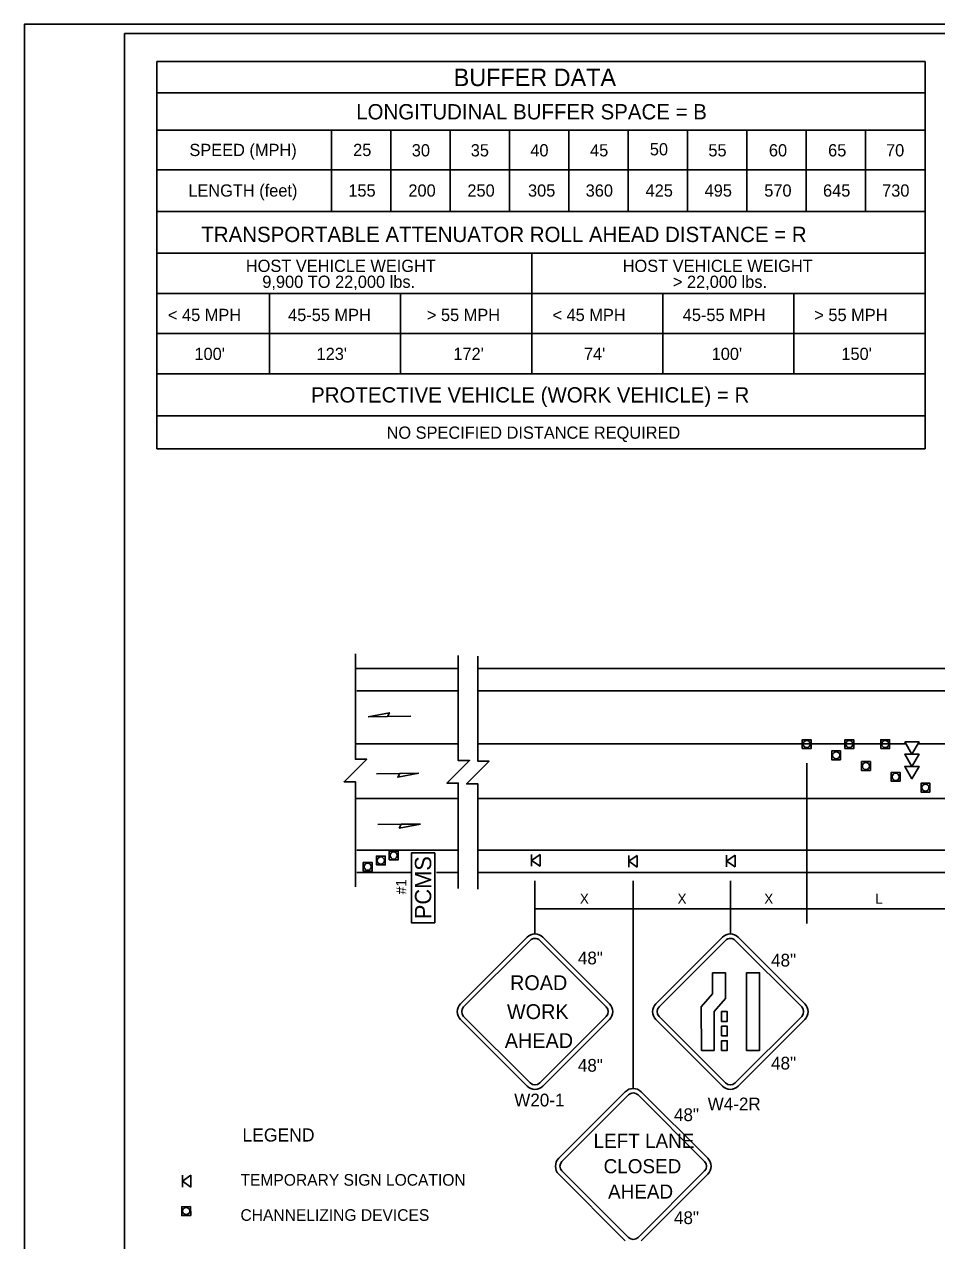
# Model space of a CAD drawing. Extents: x 99988 to 100172, y 99995 to 100047.
# Drawn here: x 99999.31 to 100005.57, y 100002.09 to 100010.44 of the extents above; entities that cross this region are included whole.
import ezdxf

# ---------------------------------------------------------------- set-up
doc = ezdxf.new("R2010")
doc.units = 0
for name, color, linetype in [('Default', 7, 'Continuous'), ('Level 15', 7, 'Continuous'), ('Level 20', 7, 'Continuous'), ('SH_DE_DetailBody1Text', 7, 'Continuous'), ('SH_DE_DetailHeading2Text', 7, 'Continuous'), ('SH_GI_PlotLimits', 7, 'Continuous'), ('SH_GI_SheetBorder', 7, 'Continuous'), ('SH_GI_TrafficMvmntArrowRt1Lane', 7, 'Continuous'), ('SH_TI_BufferDataNote', 7, 'Continuous'), ('TR_SN_WarningSigns', 7, 'Continuous'), ('TR_WZ_PortableChangeMessageSign', 7, 'Continuous'), ('TR_WZ_SequentialArrowTypeC', 7, 'Continuous'), ('TR_WZ_TrafficSafetyCone', 7, 'Continuous'), ('TR_WZ_WorkZoneDetails', 7, 'Continuous')]:
    doc.layers.add(name, color=color, linetype=linetype)

msp = doc.modelspace()

# ---------------------------------------------------------------- linework, layer by layer
at = {"layer": 'Default'}
for p, q in [((100002.2907, 100005.4964), (100001.5849, 100005.4964)), ((100005.3638, 100005.4964), (100002.4254, 100005.4964)), ((100011.7483, 100005.4964), (100005.4457, 100005.4964)), ((100002.2907, 100005.1207), (100001.5849, 100005.1207)), ((100012.5819, 100005.1207), (100002.4254, 100005.1207)), ((100002.8523, 100004.7369), (100002.7946, 100004.6967)), ((100002.7946, 100004.6565), (100002.7946, 100004.7369)), ((100002.8523, 100004.6565), (100002.8523, 100004.7369)), ((100002.8523, 100004.6565), (100002.7946, 100004.6967)), ((100003.5187, 100004.7312), (100003.4609, 100004.6909)), ((100003.4609, 100004.6507), (100003.4609, 100004.7312)), ((100003.5187, 100004.6507), (100003.4609, 100004.6909)), ((100003.5187, 100004.6507), (100003.5187, 100004.7312)), ((100004.1907, 100004.7321), (100004.133, 100004.6919)), ((100004.133, 100004.6517), (100004.133, 100004.7321)), ((100004.1907, 100004.6517), (100004.133, 100004.6919)), ((100004.1907, 100004.6517), (100004.1907, 100004.7321)), ((100000.4554, 100002.5341), (100000.3976, 100002.4938)), ((100000.3976, 100002.4536), (100000.3976, 100002.5341)), ((100000.4554, 100002.4536), (100000.3976, 100002.4938)), ((100000.4554, 100002.4536), (100000.4554, 100002.5341))]:
    msp.add_line(p, q, dxfattribs=at)
at = {"layer": 'Level 15'}
for p, q in [((100002.8174, 100004.3634), (100003.1547, 100004.3634)), ((100003.492, 100004.3634), (100003.1547, 100004.3634)), ((100003.492, 100004.3634), (100003.8252, 100004.3634)), ((100004.1585, 100004.3634), (100003.8252, 100004.3634)), ((100004.1585, 100004.3634), (100004.4206, 100004.3634)), ((100004.6827, 100004.3634), (100004.4206, 100004.3634)), ((100004.6827, 100004.3634), (100005.1813, 100004.3634)), ((100005.6799, 100004.3634), (100005.1813, 100004.3634))]:
    msp.add_line(p, q, dxfattribs=at)
at = {"layer": 'SH_GI_PlotLimits'}
msp.add_lwpolyline([(99999.3125, 99999.9375), (100015.8125, 99999.9375), (100015.8125, 100010.4375), (99999.3125, 100010.4375)], close=True, dxfattribs=at)
at = {"layer": 'SH_GI_SheetBorder'}
for q in [(100000, 100000), (100015.75, 100010.375)]:
    msp.add_line((100000, 100010.375), q, dxfattribs=at)
at = {"layer": 'SH_GI_TrafficMvmntArrowRt1Lane'}
for p, q in [((100001.8042, 100005.6842), (100001.9649, 100005.6863)), ((100001.8897, 100005.2937), (100001.7289, 100005.2916)), ((100001.8999, 100004.9445), (100001.7392, 100004.9423))]:
    msp.add_line(p, q, dxfattribs=at)
for points in [[(100001.6732, 100005.6825), (100001.8187, 100005.7101), (100001.8042, 100005.6842)], [(100002.0207, 100005.2954), (100001.8751, 100005.2678), (100001.8897, 100005.2937)], [(100002.0309, 100004.9462), (100001.8854, 100004.9186), (100001.8999, 100004.9445)]]:
    msp.add_lwpolyline(points, close=True, dxfattribs=at)
at = {"layer": 'SH_TI_BufferDataNote'}
for p, q in [((100000.2215, 100010.1819), (100005.4948, 100010.1819)), ((100000.2215, 100008.0378), (100000.2215, 100010.1819)), ((100005.4948, 100007.5218), (100005.4948, 100010.1819)), ((100000.2215, 100009.9674), (100005.4948, 100009.9674)), ((100000.2215, 100009.7102), (100005.4948, 100009.7102)), ((100001.4198, 100009.7102), (100001.4198, 100009.1529)), ((100001.8273, 100009.7102), (100001.8273, 100009.1529)), ((100002.2348, 100009.7102), (100002.2348, 100009.1529)), ((100002.6423, 100009.7102), (100002.6423, 100009.1529)), ((100003.0498, 100009.7102), (100003.0498, 100009.1529)), ((100003.4572, 100009.7102), (100003.4572, 100009.1529)), ((100003.8647, 100009.7102), (100003.8647, 100009.1529)), ((100004.2722, 100009.7102), (100004.2722, 100009.1529)), ((100004.6797, 100009.7102), (100004.6797, 100009.1529)), ((100005.0872, 100009.7102), (100005.0872, 100009.1529)), ((100000.2215, 100009.438), (100005.4948, 100009.438)), ((100000.2215, 100009.1529), (100005.4948, 100009.1529)), ((100000.2215, 100008.8658), (100005.4948, 100008.8658)), ((100002.7948, 100008.0378), (100002.7948, 100008.8634)), ((100000.2215, 100008.5898), (100005.4948, 100008.5898)), ((100000.2215, 100007.5218), (100000.2215, 100008.5898)), ((100000.995, 100008.0378), (100000.995, 100008.5898)), ((100001.895, 100008.0378), (100001.895, 100008.5898)), ((100002.795, 100008.0378), (100002.795, 100008.5898)), ((100003.695, 100008.0378), (100003.695, 100008.5898)), ((100004.595, 100008.0378), (100004.595, 100008.5898)), ((100000.2215, 100008.3138), (100005.4948, 100008.3138)), ((100000.2215, 100008.0378), (100005.4948, 100008.0378)), ((100000.2215, 100007.7498), (100005.4948, 100007.7498)), ((100000.2215, 100007.5218), (100005.4948, 100007.5218))]:
    msp.add_line(p, q, dxfattribs=at)
at = {"layer": 'TR_SN_WarningSigns'}
for p, q in [((100002.3061, 100003.7123), (100002.763, 100004.1692)), ((100002.8718, 100004.1692), (100003.3287, 100003.7123)), ((100003.6472, 100003.7123), (100004.1041, 100004.1692)), ((100004.2129, 100004.1692), (100004.6698, 100003.7123)), ((100002.3279, 100003.6905), (100002.7848, 100004.1474)), ((100002.85, 100004.1474), (100003.3069, 100003.6905)), ((100003.6689, 100003.6905), (100004.1258, 100004.1474)), ((100004.1911, 100004.1474), (100004.648, 100003.6905)), ((100002.763, 100003.1466), (100002.3061, 100003.6035)), ((100002.7847, 100003.1684), (100002.3279, 100003.6253)), ((100003.3069, 100003.6253), (100002.85, 100003.1684)), ((100003.3287, 100003.6035), (100002.8718, 100003.1466)), ((100004.1041, 100003.1466), (100003.6472, 100003.6035)), ((100004.1258, 100003.1684), (100003.6689, 100003.6253)), ((100004.648, 100003.6253), (100004.1911, 100003.1684)), ((100004.6698, 100003.6035), (100004.2129, 100003.1466)), ((100002.9807, 100002.651), (100003.4376, 100003.1079)), ((100003.0025, 100002.6292), (100003.4594, 100003.0861)), ((100003.5246, 100003.0861), (100003.9816, 100002.6292)), ((100003.5464, 100003.1079), (100004.0033, 100002.651)), ((100003.4594, 100002.1071), (100003.0025, 100002.564)), ((100003.9816, 100002.564), (100003.5246, 100002.1071)), ((100003.4376, 100002.0853), (100002.9807, 100002.5422)), ((100004.0033, 100002.5422), (100003.5464, 100002.0853))]:
    msp.add_line(p, q, dxfattribs=at)
for points in [[(100004.0353, 100003.9246), (100004.0353, 100003.7807), (100003.9575, 100003.6916), (100003.9613, 100003.3912), (100004.047, 100003.3912), (100004.047, 100003.658), (100004.1249, 100003.7471), (100004.1249, 100003.9246)], [(100004.2699, 100003.3912), (100004.3595, 100003.3912), (100004.3595, 100003.9246), (100004.2699, 100003.9246)], [(100004.0981, 100003.5912), (100004.1377, 100003.5912), (100004.1377, 100003.6579), (100004.0981, 100003.6579)], [(100004.0981, 100003.4912), (100004.1377, 100003.4912), (100004.1377, 100003.5579), (100004.0981, 100003.5579)], [(100004.0981, 100003.3912), (100004.1377, 100003.3912), (100004.1377, 100003.4579), (100004.0981, 100003.4579)]]:
    msp.add_lwpolyline(points, close=True, dxfattribs=at)
for centre, radius, start, end in [((100002.8174, 100004.1148), 0.0769, 44.99628, 134.99965), ((100002.8174, 100004.1148), 0.0462, 44.99628, 134.99965), ((100004.1585, 100004.1148), 0.0769, 44.99628, 134.99965), ((100004.1585, 100004.1148), 0.0462, 44.99628, 134.99965), ((100002.3605, 100003.6579), 0.0769, 134.99658, 224.99358), ((100002.3605, 100003.6579), 0.0462, 134.99658, 224.99358), ((100003.2743, 100003.6579), 0.0462, 314.99936, 44.99485), ((100003.2743, 100003.6579), 0.0769, 314.99936, 44.99485), ((100003.7016, 100003.6579), 0.0769, 134.99658, 224.99358), ((100003.7016, 100003.6579), 0.0462, 134.99658, 224.99358), ((100004.6154, 100003.6579), 0.0462, 314.99936, 44.99485), ((100004.6154, 100003.6579), 0.0769, 314.99936, 44.99485), ((100002.8174, 100003.201), 0.0462, 225, 314.99958), ((100004.1585, 100003.201), 0.0462, 225, 314.99958), ((100002.8174, 100003.201), 0.0769, 225, 314.99958), ((100003.492, 100003.0535), 0.0769, 44.99628, 134.99965), ((100003.492, 100003.0535), 0.0462, 44.99628, 134.99965), ((100004.1585, 100003.201), 0.0769, 225, 314.99958), ((100003.0351, 100002.5966), 0.0769, 134.99658, 224.99358), ((100003.9489, 100002.5966), 0.0769, 314.99936, 44.99485), ((100003.0351, 100002.5966), 0.0462, 134.99658, 224.99358), ((100003.9489, 100002.5966), 0.0462, 314.99936, 44.99485), ((100003.492, 100002.1397), 0.0462, 225, 314.99958)]:
    msp.add_arc(centre, radius, start, end, dxfattribs=at)
at = {"layer": 'TR_WZ_PortableChangeMessageSign'}
msp.add_lwpolyline([(100002.1294, 100004.2684), (100002.1294, 100004.7484), (100001.9694, 100004.7484), (100001.9694, 100004.2684)], close=True, dxfattribs=at)
at = {"layer": 'TR_WZ_SequentialArrowTypeC'}
msp.add_lwpolyline([(100005.3561, 100005.5096), (100005.4534, 100005.5096), (100005.4047, 100005.4257), (100005.4534, 100005.4257), (100005.4047, 100005.3417), (100005.4534, 100005.3417), (100005.4047, 100005.2577), (100005.3561, 100005.3417), (100005.4047, 100005.3417), (100005.3561, 100005.4257), (100005.4047, 100005.4257)], close=True, dxfattribs=at)
at = {"layer": 'TR_WZ_TrafficSafetyCone'}
for points in [[(100004.6523, 100005.4646), (100004.7131, 100005.4646), (100004.7131, 100005.5254), (100004.6523, 100005.5254)], [(100004.9449, 100005.4646), (100005.0056, 100005.4646), (100005.0056, 100005.5254), (100004.9449, 100005.5254)], [(100005.1912, 100005.4646), (100005.252, 100005.4646), (100005.252, 100005.5254), (100005.1912, 100005.5254)], [(100004.9154, 100005.3877), (100004.9154, 100005.4484), (100004.8546, 100005.4484), (100004.8546, 100005.3877)], [(100005.1195, 100005.3138), (100005.1195, 100005.3745), (100005.0588, 100005.3745), (100005.0588, 100005.3138)], [(100005.3237, 100005.2398), (100005.3237, 100005.3006), (100005.2629, 100005.3006), (100005.2629, 100005.2398)], [(100005.5278, 100005.1659), (100005.5278, 100005.2267), (100005.4671, 100005.2267), (100005.4671, 100005.1659)], [(100001.8171, 100004.6999), (100001.8778, 100004.6999), (100001.8778, 100004.7607), (100001.8171, 100004.7607)], [(100001.6385, 100004.6225), (100001.6992, 100004.6225), (100001.6992, 100004.6832), (100001.6385, 100004.6832)], [(100001.7288, 100004.6654), (100001.7895, 100004.6654), (100001.7895, 100004.7261), (100001.7288, 100004.7261)], [(100000.4532, 100002.3197), (100000.3924, 100002.3187), (100000.3935, 100002.2579), (100000.4542, 100002.259)]]:
    msp.add_lwpolyline(points, close=True, dxfattribs=at)
for centre in [(100004.6827, 100005.495), (100004.9753, 100005.495), (100005.2216, 100005.495), (100004.885, 100005.418), (100005.0891, 100005.3441), (100005.2933, 100005.2702), (100005.4974, 100005.1963), (100001.8475, 100004.7303), (100001.6689, 100004.6529), (100001.7591, 100004.6957), (100000.4233, 100002.2888)]:
    msp.add_circle(centre, 0.0244, dxfattribs=at)
at = {"layer": 'TR_WZ_WorkZoneDetails'}
for p, q in [((100002.2907, 100006.0142), (100001.5855, 100006.0142)), ((100007.3972, 100006.0142), (100002.4293, 100006.0142)), ((100002.2896, 100005.8608), (100001.5952, 100005.8608)), ((100007.3972, 100005.8608), (100002.4254, 100005.8608)), ((100004.6827, 100004.2635), (100004.6827, 100005.3646)), ((100002.291, 100004.7676), (100001.5952, 100004.7676)), ((100011.7483, 100004.7676), (100002.4278, 100004.7676)), ((100001.9652, 100004.6142), (100001.5936, 100004.6142)), ((100002.2907, 100004.6142), (100002.1423, 100004.6142)), ((100011.7483, 100004.6142), (100002.4307, 100004.6142)), ((100002.8174, 100004.1917), (100002.8174, 100004.5565)), ((100003.492, 100003.1304), (100003.492, 100004.5565)), ((100004.1585, 100004.1917), (100004.1585, 100004.5565))]:
    msp.add_line(p, q, dxfattribs=at)
for points in [[(100001.5849, 100006.1142), (100001.5849, 100005.3916), (100001.6624, 100005.3916), (100001.5075, 100005.2368), (100001.5849, 100005.2368), (100001.5849, 100004.5142)], [(100002.2907, 100006.1045), (100002.2907, 100005.3819), (100002.3682, 100005.3819), (100002.2133, 100005.2271), (100002.2907, 100005.2271), (100002.2907, 100004.5045)], [(100002.4254, 100006.0996), (100002.4254, 100005.3771), (100002.5028, 100005.3771), (100002.348, 100005.2222), (100002.4254, 100005.2222), (100002.4254, 100004.4996)]]:
    msp.add_lwpolyline(points, dxfattribs=at)

# ---------------------------------------------------------------- texts
at = {"layer": 'Level 20'}
for s, rotation, p in [('#1', 90, (100001.9344, 100004.4634)), ('X', 360, (100003.125, 100004.3984)), ('X', 360, (100003.7955, 100004.3984))]:
    msp.add_text(s, height=0.07, rotation=rotation, dxfattribs=at).set_placement(p)
for s, p in [('X', (100004.3909, 100004.3984)), ('L', (100005.1522, 100004.3984))]:
    msp.add_text(s, height=0.07, dxfattribs=at).set_placement(p)
at = {"layer": 'SH_DE_DetailBody1Text'}
for s, p in [('TEMPORARY SIGN LOCATION', (100000.7962, 100002.4627)), ('CHANNELIZING DEVICES', (100000.7962, 100002.2214))]:
    msp.add_text(s, height=0.08, dxfattribs=at).set_placement(p)
at = {"layer": 'SH_DE_DetailHeading2Text'}
msp.add_text('LEGEND', height=0.09, dxfattribs=at).set_placement((100000.8094, 100002.7662))
at = {"layer": 'SH_TI_BufferDataNote'}
for s, height, p in [('BUFFER DATA', 0.12, (100002.2594, 100010.0134)), ('LONGITUDINAL BUFFER SPACE = B', 0.105, (100001.5902, 100009.7846)), ('SPEED (MPH)', 0.084, (100000.4456, 100009.533)), ('25', 0.084, (100001.5693, 100009.533)), ('30', 0.084, (100001.9719, 100009.5306)), ('35', 0.084, (100002.3766, 100009.5306)), ('40', 0.084, (100002.7854, 100009.5306)), ('45', 0.084, (100003.1956, 100009.5306)), ('50', 0.084, (100003.6058, 100009.5377)), ('55', 0.084, (100004.0075, 100009.5306)), ('60', 0.084, (100004.423, 100009.5306)), ('65', 0.084, (100004.8295, 100009.5306)), ('70', 0.084, (100005.227, 100009.5306)), ('LENGTH (feet)', 0.084, (100000.438, 100009.2544)), ('155', 0.084, (100001.5362, 100009.2544)), ('200', 0.084, (100001.9485, 100009.2544)), ('250', 0.084, (100002.3534, 100009.2544)), ('305', 0.084, (100002.7695, 100009.2544)), ('360', 0.084, (100003.1654, 100009.2544)), ('425', 0.084, (100003.5766, 100009.2544)), ('495', 0.084, (100003.9818, 100009.2544)), ('570', 0.084, (100004.3912, 100009.2544)), ('645', 0.084, (100004.7946, 100009.2544)), ('730', 0.084, (100005.2003, 100009.2544)), ('TRANSPORTABLE ATTENUATOR ROLL AHEAD DISTANCE = R', 0.105, (100000.5273, 100008.9425)), ('HOST VEHICLE WEIGHT', 0.084, (100000.8328, 100008.7371)), ('HOST VEHICLE WEIGHT', 0.084, (100003.4196, 100008.7371)), ('9,900 TO 22,000 lbs.', 0.084, (100000.9458, 100008.6278)), ('> 22,000 lbs.', 0.084, (100003.764, 100008.6278)), ('< 45 MPH', 0.084, (100000.2982, 100008.4)), ('45-55 MPH', 0.084, (100001.1228, 100008.4)), ('> 55 MPH', 0.084, (100002.0754, 100008.4)), ('< 45 MPH', 0.084, (100002.9374, 100008.4)), ('45-55 MPH', 0.084, (100003.8317, 100008.4)), ('> 55 MPH', 0.084, (100004.7347, 100008.4)), ("100'", 0.084, (100000.48, 100008.1327)), ("123'", 0.084, (100001.3184, 100008.1327)), ("172'", 0.084, (100002.2572, 100008.1327)), ("74'", 0.084, (100003.1538, 100008.1327)), ("100'", 0.084, (100004.0301, 100008.1327)), ("150'", 0.084, (100004.9204, 100008.1327)), ('PROTECTIVE VEHICLE (WORK VEHICLE) = R', 0.105, (100001.2807, 100007.8407)), ('NO SPECIFIED DISTANCE REQUIRED', 0.084, (100001.7986, 100007.5919))]:
    msp.add_text(s, height=height, dxfattribs=at).set_placement(p)
at = {"layer": 'TR_SN_WarningSigns'}
for s, height, p in [('48"', 0.0875, (100003.1119, 100003.9827)), ('48"', 0.0875, (100004.438, 100003.9677)), ('ROAD', 0.10176, (100002.6462, 100003.8057)), ('WORK', 0.10176, (100002.6252, 100003.6071)), ('AHEAD', 0.10176, (100002.6099, 100003.4084)), ('48"', 0.0875, (100003.1119, 100003.2457)), ('48"', 0.0875, (100004.438, 100003.2606)), ('W20-1', 0.0875, (100002.675, 100003.0073)), ('W4-2R', 0.0875, (100004.0029, 100002.9803)), ('48"', 0.0875, (100003.7716, 100002.9064)), ('LEFT LANE', 0.09691, (100003.2198, 100002.7226)), ('CLOSED', 0.09691, (100003.2887, 100002.5481)), ('AHEAD', 0.09691, (100003.3191, 100002.3737)), ('48"', 0.0875, (100003.7716, 100002.1993))]:
    msp.add_text(s, height=height, dxfattribs=at).set_placement(p)
at = {"layer": 'TR_WZ_PortableChangeMessageSign'}
msp.add_text('PCMS', height=0.112, rotation=90, dxfattribs=at).set_placement((100002.1054, 100004.2929))

doc.saveas('drawing.dxf')
